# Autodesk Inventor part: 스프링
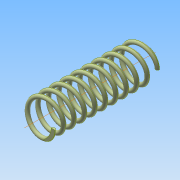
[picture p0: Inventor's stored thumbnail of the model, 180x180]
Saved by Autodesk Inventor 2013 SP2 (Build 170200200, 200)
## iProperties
Created: 2023-11
Part Number: 스프링
Material: 강철, 연강
Document SubType Name: Modeling
Designer: mdu-01
Density: 1 g/cm^3
Author: mdu-01
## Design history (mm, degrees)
sketch "스케치1" dims "d0" = 0.6
  geometry: L1 (0, 0)-(2.35, 0); L2 (2.35, 0)-(2.35, 16); L3 (2.35, 16)-(0, 16); L4 (0, 16)-(0, 0); L5 (-2.75, 16)-(2.75, 16) reference; L6 (2.65, 0)-(2.65, 6.462); 1 further point
  constraints: 10 end point, 2 parallel, 2 perpendicular, 1 coincident, 1 collinear, 1 horizontal, 1 horizontal alignment, 1 vertical, 2 other
  dimensions: "d2" = 16 distance between parallel lines of L1 L3 (derived); "d16" = 0.1 distance from line of L5.end L6
feature "코일1" sketch "스케치1" pitch "d3" = 10; turns "d5" = 10; dims "d4" = 16 (= d2), "d6" = 0, angle "d7" = 90 deg, angle "d8" = 90 deg, "d9" = 0, "d10" = 0
sketch "스케치2"
  geometry: L1 (-2.65, 0)-(-2.05, 0) reference; 1 further point
  constraints: 1 horizontal alignment
extrude "돌출1" cut sketch "스케치2" stored distance "d11" = 0; taper "d12" = 0 deg
node "작업 평면1"
sketch "스케치3"
  geometry: L1 (0.3, 0)-(-0.3, 0) reference; 1 further point
  constraints: 1 horizontal alignment
extrude "돌출2" cut sketch "스케치3" stored distance "d14" = 0; taper "d15" = 0 deg
node "솔리드1"
node "참조1"
node "절단 모서리 투영1"
node "절단 모서리 투영2"
other parameters: "d13" = 0
